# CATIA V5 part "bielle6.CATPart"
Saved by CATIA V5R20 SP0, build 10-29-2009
Part number: bielle6
Bounding box of the stored display mesh (mm): x 8 to 26, y -60 to -40, z -10 to 50
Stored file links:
  D:\Dropbox\IAO_2012\IAO_2012_991_jambrosino\IAO_2012_991_jambrosino_Catia\Assemblage\bielle6.CATPart
  D:\Dropbox\IAO_2012\IAO_2012_991_jambrosino\IAO_2012_991_jambrosino_Catia\Assemblage\Ass_IAO_991_skl.CATProduct
  J:\IAO_Mecanisme_991\IAO_Mecanisme_991_CATIA\skl_bielle_6.CATPart
  D:\Dropbox\IAO_2012\IAO_2012_991_jambrosino\IAO_2012_991_jambrosino_Catia\Assemblage\bielle2bis.CATPart
  D:\Dropbox\IAO_2012\IAO_2012_991_jambrosino\IAO_2012_991_jambrosino_Catia\Assemblage\bielle7.CATPart
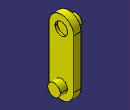
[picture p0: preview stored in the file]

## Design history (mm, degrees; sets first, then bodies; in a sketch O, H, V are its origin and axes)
Set1
  Plane1 "plan_ref_yz": linked copy from another document
  DatumSurface1: linked copy from another document
  DatumPoint1: linked copy from another document
  DatumPoint2: linked copy from another document
  Plane2: linked copy from another document
  DatumCurve1: linked copy from another document
Body1 (main body)
  Plane3: type Offset, RefPlane Plane1, Offset 20
  Sketch1 on Plane3, origin (20, 0, 0), H (0, 1, 0), V (0, 0, 1)
    line L1 (-40, 40) -> (-40, 0)
    line L2 (-60, 0) -> (-60, 40)
    arc A1 centre (-50, 40) radius 10 from (-40, 40) to (-60, 40) ccw
    point P5 (-50, 40)
    arc A2 centre (-50, 0) radius 10 from (-60, 0) to (-40, 0) ccw
    point P6 (-50, 0)
    circle A3 centre (-50, 40) radius 5
    point P7 (-50, 40)
    circle A4 centre (-50, 0) radius 5
    point P8 (-50, 0)
    reference projected point E1 (-50, 40) from vertex of DatumPoint1
    reference projected point E2 (-50, 0) from DatumPoint2
    radius A1 = 10
    radius A3 = 5
    radius A4 = 5
    vertical: L1 V, L2 V
    tangency: A1 L1, A1 L2, L2 A2, L1 A2
    coincidence: P7 P5, P8 P6, P7 E1, P8 E2
  Pad1: profile Sketch1, direction (-1, 0, 0), length 6
  Sketch2 on end face of Pad1, origin (14, 0, 0), H (0, -1, 0), V (0, 0, 1)
    circle A1 centre (50, 40) radius 5
    point P1 (50, 40)
    reference projected point E1 (50, 40) from DatumPoint1
    reference projected circle E2 centre (50, 40) radius 5 from edge [face of Pad1 from Sketch1.A3 | end face of Pad1]
    coincidence: P1 E1, A1 E2
  Pad2: profile Sketch2, direction (-1, 0, 0), length 6, opposite side length 4
  Sketch3 on Plane2, origin (20, 0, 0), H (0, -1, 0), V (0, 0, 1)
    circle A1 centre (50, 0) radius 5
    reference projected circle E1 centre (50, 0) radius 5 from edge of DatumCurve1
    coincidence: A1 E1
  Pad3: profile Sketch3, direction (-1, 0, 0), length 4, opposite side length 6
